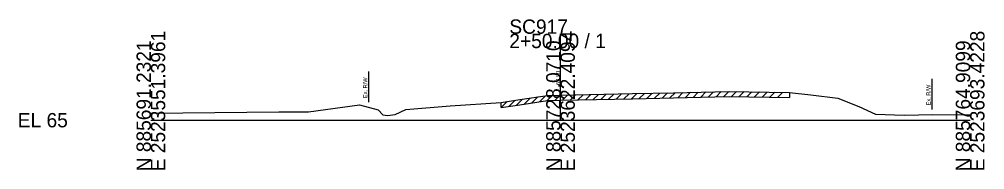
# Model space of a CAD drawing. Extents: x -26 to 218, y -10 to 12021.
# Drawn here: x -25.7 to 162.8, y 2490.3 to 2519.7 of the extents above; entities that cross this region are included whole.
import ezdxf

# ---------------------------------------------------------------- set-up
doc = ezdxf.new("R2010")
doc.units = 0
for name, color, linetype in [('RD_GPK_XS_Cell', 7, 'Continuous'), ('RD_XS_ExGround', 7, 'Continuous'), ('RD_XS_ExPaveRet', 7, 'Continuous'), ('RD_XS_ExRW', 7, 'Continuous'), ('RD_XS_TX_Elev_EX', 7, 'Continuous')]:
    doc.layers.add(name, color=color, linetype=linetype)

msp = doc.modelspace()

# ---------------------------------------------------------------- linework, layer by layer
at = {"layer": 'RD_GPK_XS_Cell'}
for p, q in [((80, 2500), (80, 2516.9)), ((0, 2500), (80, 2500)), ((80, 2500), (160, 2500))]:
    msp.add_line(p, q, dxfattribs=at)
at = {"layer": 'RD_XS_ExGround'}
for p, q in [((110.17, 2505.57), (112.98, 2505.63)), ((112.98, 2505.63), (116.77, 2505.56)), ((68.38, 2503.45), (72.08, 2504.03)), ((72.08, 2504.03), (77.45, 2504.85)), ((77.45, 2504.85), (80, 2504.9)), ((80, 2504.9), (94.06, 2505.19)), ((94.06, 2505.19), (102.04, 2505.37)), ((102.04, 2505.37), (110.17, 2505.57)), ((116.77, 2505.56), (124.72, 2505.42)), ((124.72, 2505.42), (128.91, 2504.95)), ((128.91, 2504.95), (134.18, 2504.31)), ((134.18, 2504.31), (138.25, 2502.66)), ((30.78, 2501.64), (40.76, 2503.02)), ((40.76, 2503.02), (44.36, 2502.02)), ((44.36, 2502.02), (45.33, 2501.04)), ((47.71, 2501.14), (49.77, 2502.09)), ((49.77, 2502.09), (58.45, 2502.81)), ((58.45, 2502.81), (68.38, 2503.45)), ((138.25, 2502.66), (141.51, 2501.19)), ((0, 2501.34), (24.98, 2501.65)), ((24.98, 2501.65), (30.78, 2501.64)), ((45.33, 2501.04), (46.22, 2500.9)), ((46.22, 2500.9), (47.71, 2501.14)), ((141.51, 2501.19), (147.09, 2500.97)), ((147.09, 2500.97), (152.69, 2501.11)), ((152.69, 2501.11), (160, 2501.05))]:
    msp.add_line(p, q, dxfattribs=at)
at = {"layer": 'RD_XS_ExPaveRet'}
for p, q in [((111.88, 2504.61), (112.9, 2505.63)), ((113.38, 2504.62), (114.36, 2505.61)), ((69.88, 2502.68), (71.06, 2503.87)), ((71.38, 2502.92), (72.56, 2504.1)), ((72.08, 2503.03), (77.45, 2503.85)), ((72.88, 2503.15), (74.06, 2504.33)), ((74.38, 2503.38), (75.56, 2504.56)), ((75.88, 2503.61), (77.06, 2504.79)), ((77.38, 2503.84), (78.41, 2504.87)), ((77.45, 2503.85), (80, 2503.9)), ((78.88, 2503.88), (79.9, 2504.9)), ((80, 2503.9), (94.06, 2504.19)), ((80.38, 2503.91), (81.4, 2504.93)), ((81.88, 2503.94), (82.9, 2504.96)), ((83.38, 2503.97), (84.4, 2504.99)), ((84.88, 2504), (85.9, 2505.02)), ((86.38, 2504.03), (87.4, 2505.05)), ((87.88, 2504.06), (88.9, 2505.08)), ((89.38, 2504.09), (90.4, 2505.11)), ((90.88, 2504.12), (91.9, 2505.14)), ((92.38, 2504.15), (93.4, 2505.17)), ((93.88, 2504.18), (94.9, 2505.2)), ((94.06, 2504.19), (102.04, 2504.37)), ((95.38, 2504.22), (96.4, 2505.24)), ((96.88, 2504.25), (97.9, 2505.27)), ((98.38, 2504.29), (99.4, 2505.31)), ((99.88, 2504.32), (100.9, 2505.34)), ((101.38, 2504.35), (102.4, 2505.38)), ((102.04, 2504.37), (110.17, 2504.57)), ((102.88, 2504.39), (103.9, 2505.41)), ((104.38, 2504.43), (105.4, 2505.45)), ((105.88, 2504.46), (106.9, 2505.49)), ((107.38, 2504.5), (108.4, 2505.52)), ((108.88, 2504.54), (109.9, 2505.56)), ((110.17, 2504.57), (112.98, 2504.63)), ((110.38, 2504.57), (111.4, 2505.6)), ((112.98, 2504.63), (116.77, 2504.56)), ((114.88, 2504.6), (115.86, 2505.58)), ((116.38, 2504.57), (117.36, 2505.55)), ((116.77, 2504.56), (124.72, 2504.42)), ((117.88, 2504.54), (118.86, 2505.52)), ((119.38, 2504.51), (120.36, 2505.49)), ((120.88, 2504.49), (121.86, 2505.47)), ((122.38, 2504.46), (123.36, 2505.44)), ((124.72, 2505.42), (124.72, 2504.42)), ((68.38, 2502.45), (69.56, 2503.63)), ((68.38, 2502.45), (68.38, 2503.45)), ((68.38, 2502.45), (72.08, 2503.03))]:
    msp.add_line(p, q, dxfattribs=at)
at = {"layer": 'RD_XS_ExRW'}
for p, q in [((42.5, 2509.54), (42.5, 2503.54)), ((152.51, 2508.1), (152.51, 2502.1))]:
    msp.add_line(p, q, dxfattribs=at)

# ---------------------------------------------------------------- texts
at = {"layer": 'RD_GPK_XS_Cell'}
for s, p in [('SC917', (70, 2516.9)), ('2+50.00 / 1', (70, 2514.1)), ('EL 65', (-26, 2498.6))]:
    msp.add_text(s, height=2.8, dxfattribs=at).set_placement(p)
for s, p in [('E 2523551.3961', (2.8, 2490)), ('E 2523622.4094', (82.8, 2490)), ('E 2523693.4228', (162.8, 2490)), ('N 885691.2321', (0, 2490)), ('N 885728.0710', (80, 2490)), ('N 885764.9099', (160, 2490))]:
    msp.add_text(s, height=2.8, rotation=90, dxfattribs=at).set_placement(p)
at = {"layer": 'RD_XS_ExRW'}
for p in [(42.25, 2504.32), (152.26, 2502.89)]:
    msp.add_text('Ex. R/W ', height=0.8, rotation=90, dxfattribs=at).set_placement(p)
at = {"layer": 'RD_XS_TX_Elev_EX'}
msp.add_text('69.90', height=0.8, rotation=90, dxfattribs=at).set_placement((79.9, 2506.9))

doc.saveas('drawing.dxf')
